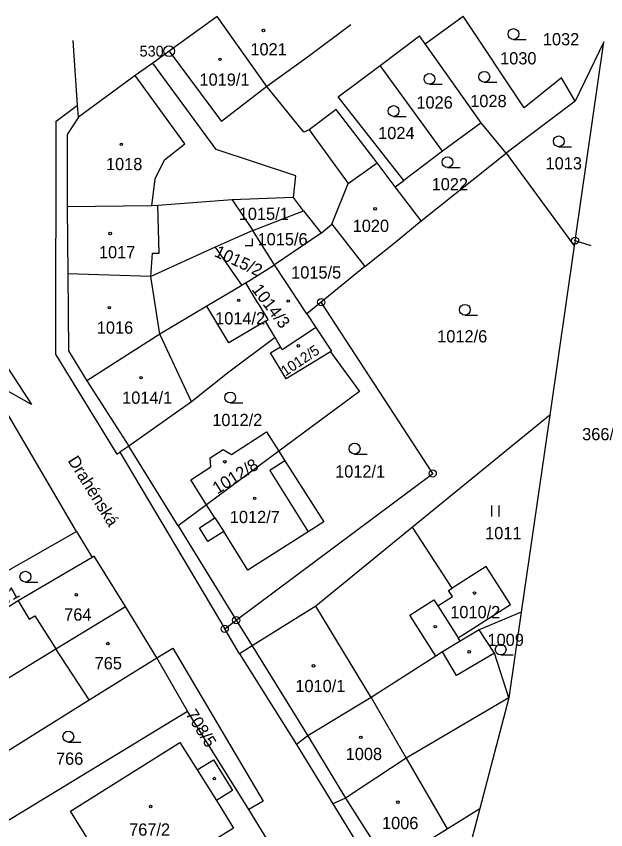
# Model space of a CAD drawing. Extents: x -776701 to -776081, y -974398 to -973771.
# Drawn here: x -776229.3 to -776147.4, y -973884.4 to -973771.3 of the extents above; entities that cross this region are included whole.
import ezdxf

# ---------------------------------------------------------------- set-up
doc = ezdxf.new("R2010")
doc.units = 0
for name, color, linetype in [('Hranice parcel', 7, 'Continuous'), ('Parcelní čísla', 7, 'Continuous'), ('Pop  PČ popisy', 7, 'Continuous'), ('Vnitřní kresba', 7, 'Continuous'), ('Značky bodu BP', 7, 'Continuous'), ('Značky budov', 7, 'Continuous'), ('Značky kultur', 7, 'Continuous')]:
    doc.layers.add(name, color=color, linetype=linetype)

msp = doc.modelspace()

# ---------------------------------------------------------------- linework, layer by layer
at = {"layer": 'Hranice parcel'}
for p, q in [((-776172.49, -973775.13), (-776167.2, -973771.3)), ((-776178.76, -973778.12), (-776173.27, -973774.04)), ((-776172.49, -973775.13), (-776173.27, -973774.04)), ((-776164.68, -973786.09), (-776172.49, -973775.13)), ((-776147.65, -973774.86), (-776151.65, -973783.1)), ((-776151.65, -973802.49), (-776147.65, -973774.86)), ((-776184.58, -973782.52), (-776178.76, -973778.12)), ((-776170.09, -973790.04), (-776178.76, -973778.12)), ((-776151.65, -973783.1), (-776153.52, -973779.87)), ((-776175.47, -973794.11), (-776184.58, -973782.52)), ((-776151.65, -973783.1), (-776161.22, -973790.34)), ((-776164.68, -973786.09), (-776170.09, -973790.04)), ((-776161.22, -973790.34), (-776164.68, -973786.09)), ((-776170.09, -973790.04), (-776175.47, -973794.11)), ((-776173.06, -973799.74), (-776161.22, -973790.34)), ((-776161.22, -973790.34), (-776151.75, -973803.2)), ((-776176.66, -973795.02), (-776179.17, -973791.67)), ((-776176.66, -973795.02), (-776175.47, -973794.11)), ((-776173.06, -973799.74), (-776176.66, -973795.02)), ((-776190.82, -973796.5), (-776199.31, -973796.81)), ((-776189.4, -973798.32), (-776190.82, -973796.5)), ((-776222.25, -973797.77), (-776222.17, -973807.08)), ((-776199.31, -973796.81), (-776196.44, -973801.08)), ((-776196.44, -973801.08), (-776189.4, -973798.32)), ((-776189.4, -973798.32), (-776186.97, -973801.45)), ((-776196.44, -973801.08), (-776201.7, -973803.4)), ((-776193.42, -973805.85), (-776196.44, -973801.08)), ((-776186.97, -973801.45), (-776185.48, -973800.19)), ((-776185.48, -973800.19), (-776180.86, -973806.09)), ((-776186.97, -973801.45), (-776193.42, -973805.85)), ((-776201.7, -973803.4), (-776198, -973808.7)), ((-776151.75, -973803.2), (-776155.16, -973826.72)), ((-776151.65, -973802.49), (-776151.75, -973803.2)), ((-776149.4, -973803.23), (-776151.65, -973802.49)), ((-776197.42, -973808.34), (-776193.42, -973805.85)), ((-776188.94, -973812.67), (-776193.42, -973805.85)), ((-776180.86, -973806.09), (-776186.94, -973811.04)), ((-776198, -973808.7), (-776202.85, -973811.59)), ((-776197.42, -973808.34), (-776198, -973808.7)), ((-776186.94, -973811.04), (-776188.94, -973812.67)), ((-776193.35, -973815.97), (-776194.71, -973813.67)), ((-776188.94, -973812.67), (-776187.7, -973814.57)), ((-776187.7, -973814.57), (-776185.53, -973817.87)), ((-776192.6, -973817.25), (-776193.35, -973815.97)), ((-776192.37, -973817.64), (-776192.6, -973817.25)), ((-776185.67, -973817.96), (-776191.83, -973821.7)), ((-776185.53, -973817.87), (-776185.67, -973817.96)), ((-776185.67, -973817.96), (-776181.61, -973823.44)), ((-776220.95, -973842.92), (-776233.34, -973821.83)), ((-776219.55, -973821.99), (-776213.69, -973831.04)), ((-776181.61, -973823.44), (-776192.82, -973831.75)), ((-776155.16, -973826.72), (-776174.27, -973842.32)), ((-776155.16, -973826.72), (-776159.12, -973854.12)), ((-776213.69, -973831.04), (-776214.95, -973831.9)), ((-776206.84, -973842.14), (-776213.69, -973831.04)), ((-776192.82, -973831.75), (-776202.88, -973839.2)), ((-776214.95, -973831.9), (-776200.36, -973856.43)), ((-776202.88, -973839.2), (-776206.84, -973842.14)), ((-776239.75, -973853.59), (-776220.95, -973842.92)), ((-776220.95, -973842.92), (-776218.81, -973846.53)), ((-776168.75, -973850.8), (-776174.27, -973842.32)), ((-776209.82, -973860.47), (-776214.18, -973853.35)), ((-776159.12, -973854.12), (-776164.99, -973856.56)), ((-776159.12, -973854.12), (-776160.84, -973866.04)), ((-776198.3, -973859.9), (-776200.36, -973856.43)), ((-776164.99, -973856.56), (-776167.63, -973858.16)), ((-776196.54, -973858.82), (-776198.3, -973859.9)), ((-776209.82, -973860.47), (-776207.58, -973859.13)), ((-776198.3, -973859.9), (-776190.39, -973872.52)), ((-776205.52, -973867.88), (-776209.82, -973860.47)), ((-776160.84, -973866.04), (-776164.9, -973881.43)), ((-776232.47, -973884.28), (-776205.52, -973867.88)), ((-776196.99, -973881.56), (-776205.52, -973867.88)), ((-776190.39, -973872.52), (-776185.35, -973880.74)), ((-776183.56, -973879.96), (-776185.35, -973880.74)), ((-776194.35, -973885.85), (-776196.99, -973881.56)), ((-776185.35, -973880.74), (-776170.9, -973904.16)), ((-776164.9, -973881.43), (-776170.9, -973904.16))]:
    msp.add_line(p, q, dxfattribs=at)
for points in [[(-776201.43, -973771.33), (-776208.1, -973776.15), (-776210.36, -973777.84)], [(-776179.17, -973791.67), (-776184.88, -973784.25), (-776188.6, -973787.1), (-776189.35, -973787.43), (-776194.52, -973781.04), (-776201.43, -973771.33)], [(-776153.52, -973779.87), (-776158.72, -973784.02), (-776167.2, -973771.3)], [(-776220.7, -973785.33), (-776220.82, -973783.65), (-776221.44, -973774.68)], [(-776210.36, -973777.84), (-776212.82, -973779.52), (-776220.7, -973785.33)], [(-776190.82, -973796.5), (-776190.45, -973793.46), (-776201.56, -973789.82), (-776210.36, -973777.84)], [(-776220.7, -973785.33), (-776222.26, -973787.71), (-776222.25, -973797.77)], [(-776185.48, -973800.19), (-776183.2, -973794.54), (-776179.17, -973791.67)], [(-776199.31, -973796.81), (-776209.67, -973797.62), (-776210.48, -973797.65), (-776222.25, -973797.77)], [(-776180.86, -973806.09), (-776176.8, -973802.85), (-776173.06, -973799.74)], [(-776201.7, -973803.4), (-776210.65, -973807.48), (-776222.17, -973807.08)], [(-776222.17, -973807.08), (-776222.09, -973817.78), (-776219.55, -973821.99)], [(-776194.71, -973813.67), (-776194.34, -973813.45), (-776195.48, -973811.56), (-776195.93, -973810.83), (-776197.42, -973808.34)], [(-776200.36, -973856.43), (-776198.76, -973855.23), (-776171.44, -973834.84), (-776186.94, -973811.04)], [(-776202.85, -973811.59), (-776209.39, -973815.48), (-776219.55, -973821.99)], [(-776194.71, -973813.67), (-776199.77, -973816.7), (-776202.85, -973811.59)], [(-776187.7, -973814.57), (-776188.03, -973814.78), (-776192.37, -973817.64)], [(-776193.35, -973815.97), (-776199.99, -973820.9), (-776205, -973824.9), (-776213.69, -973831.04)], [(-776191.83, -973821.7), (-776194, -973818.08), (-776192.6, -973817.25)], [(-776231.27, -973819.06), (-776227.23, -973825.26), (-776233.34, -973821.83)], [(-776202.88, -973839.2), (-776205.07, -973835.71), (-776202.31, -973833.94), (-776202.38, -973832.68), (-776200.57, -973831.53), (-776199.44, -973832.2), (-776194.54, -973829.06), (-776192.82, -973831.75)], [(-776192.82, -973831.75), (-776191.98, -973833.08), (-776186.58, -973841.55), (-776188.78, -973842.95), (-776197.16, -973848.28), (-776200.5, -973842.93), (-776202.71, -973844.28), (-776203.86, -973842.4), (-776201.75, -973841), (-776202.88, -973839.2)], [(-776174.27, -973842.32), (-776187.69, -973853.27), (-776196.54, -973858.82)], [(-776218.81, -973846.53), (-776229.07, -973852.55), (-776233.95, -973855.6), (-776237.38, -973857.77)], [(-776214.18, -973853.35), (-776218.51, -973846.33), (-776218.81, -973846.53)], [(-776167.63, -973858.16), (-776167.92, -973857.69), (-776160.63, -973853.06), (-776163.99, -973847.77), (-776168.75, -973850.8)], [(-776170.99, -973860.22), (-776174.64, -973854.54), (-776171.27, -973852.4), (-776170.73, -973853.25), (-776168.69, -973851.95), (-776169.23, -973851.1), (-776168.75, -973850.8)], [(-776240.99, -973869.69), (-776238.41, -973868.12), (-776223.83, -973859.23), (-776214.18, -973853.35)], [(-776160.84, -973866.04), (-776162.87, -973859.82), (-776164.99, -973856.56)], [(-776167.63, -973858.16), (-776170.07, -973859.63), (-776170.99, -973860.22)], [(-776207.58, -973859.13), (-776195, -973880.4), (-776196.99, -973881.56)], [(-776236.37, -973876.99), (-776219.2, -973866.3), (-776209.82, -973860.47)], [(-776170.99, -973860.22), (-776180, -973866), (-776188.82, -973871.31), (-776190.39, -973872.52)], [(-776160.84, -973866.04), (-776175.11, -973874.42), (-776183.56, -973879.96)], [(-776221.8, -973881.78), (-776206.58, -973872.23), (-776204.18, -973876.06), (-776201.92, -973874.65), (-776199.26, -973878.91), (-776201.52, -973880.32), (-776199.13, -973884.16), (-776214.43, -973893.65), (-776221.8, -973881.78)], [(-776183.56, -973879.96), (-776177.64, -973889.3), (-776169.41, -973884.22), (-776164.9, -973881.43)]]:
    msp.add_lwpolyline(points, dxfattribs=at)
at = {"layer": 'Vnitřní kresba'}
for p, q in [((-776182.84, -973772.51), (-776188.88, -973777.04)), ((-776208.1, -973776.15), (-776200.79, -973785.93)), ((-776188.88, -973777.04), (-776194.52, -973781.04)), ((-776205.91, -973789.03), (-776212.82, -973779.52)), ((-776194.52, -973781.04), (-776200.79, -973785.93)), ((-776223.8, -973785.86), (-776220.82, -973783.65)), ((-776223.85, -973818.37), (-776223.8, -973785.86)), ((-776188.6, -973787.1), (-776183.2, -973794.54)), ((-776208.72, -973791.24), (-776205.91, -973789.03)), ((-776210.01, -973793.89), (-776208.72, -973791.24)), ((-776210.48, -973797.65), (-776210.01, -973793.89)), ((-776209.49, -973804.22), (-776209.67, -973797.62)), ((-776210.65, -973807.48), (-776210.39, -973804.24)), ((-776210.39, -973804.24), (-776209.49, -973804.22)), ((-776209.39, -973815.48), (-776210.65, -973807.48)), ((-776205, -973824.9), (-776209.39, -973815.48)), ((-776223.85, -973818.37), (-776215.37, -973832.18)), ((-776215.37, -973832.18), (-776214.95, -973831.9)), ((-776201.75, -973841), (-776200.5, -973842.93)), ((-776206.84, -973842.14), (-776198.76, -973855.23)), ((-776229.07, -973852.55), (-776227.57, -973855.11)), ((-776180, -973866), (-776187.69, -973853.27)), ((-776170.73, -973853.25), (-776167.92, -973857.69)), ((-776227.57, -973855.11), (-776226.76, -973854.64)), ((-776226.76, -973854.64), (-776223.83, -973859.23)), ((-776198.76, -973855.23), (-776196.54, -973858.82)), ((-776196.54, -973858.82), (-776188.82, -973871.31)), ((-776219.2, -973866.3), (-776223.83, -973859.23)), ((-776168.11, -973862.93), (-776170.07, -973859.63)), ((-776162.87, -973859.82), (-776168.11, -973862.93)), ((-776180, -973866), (-776175.11, -973874.42)), ((-776188.82, -973871.31), (-776183.56, -973879.96)), ((-776175.11, -973874.42), (-776169.41, -973884.22)), ((-776204.18, -973876.06), (-776201.52, -973880.32))]:
    msp.add_line(p, q, dxfattribs=at)
msp.add_lwpolyline([(-776191.98, -973833.08), (-776194.09, -973834.42), (-776188.78, -973842.95)], dxfattribs=at)
at = {"layer": 'Značky bodu BP'}
for centre, radius in [((-776208.1, -973776.15), 0.75), ((-776208.1, -973776.15), 0.03), ((-776151.65, -973802.49), 0.5), ((-776151.65, -973802.49), 0.0303), ((-776186.94, -973811.04), 0.5), ((-776186.94, -973811.04), 0.0303), ((-776171.44, -973834.84), 0.5), ((-776171.44, -973834.84), 0.0303), ((-776198.76, -973855.23), 0.5), ((-776198.76, -973855.23), 0.0303), ((-776200.36, -973856.43), 0.5), ((-776200.36, -973856.43), 0.0303)]:
    msp.add_circle(centre, radius, dxfattribs=at)
at = {"layer": 'Značky budov'}
for centre in [(-776194.98, -973773.27), (-776201.02, -973777.28), (-776214.73, -973789.1), (-776179.44, -973798.06), (-776216.29, -973801.49), (-776198.42, -973810.79), (-776191.53, -973810.87), (-776216.4, -973811.81), (-776190.13, -973817.1), (-776212, -973821.53), (-776200.34, -973833.22), (-776196.2, -973838.3), (-776220.99, -973851.72), (-776165.62, -973851.47), (-776171.09, -973856.14), (-776216.61, -973858.49), (-776166.36, -973859.64), (-776188.02, -973861.58), (-776181.44, -973871.52), (-776201.8, -973877.25), (-776176.28, -973880.53), (-776210.66, -973881.13)]:
    msp.add_circle(centre, 0.175, dxfattribs=at)
at = {"layer": 'Značky kultur'}
for p, q in [((-776160.21, -973774.52), (-776158.46, -973774.52)), ((-776171.89, -973780.75), (-776170.14, -973780.75)), ((-776164.27, -973780.46), (-776162.52, -973780.46)), ((-776176.88, -973785.22), (-776175.13, -973785.22)), ((-776153.91, -973789.43), (-776152.16, -973789.43)), ((-776169.39, -973792.33), (-776167.64, -973792.33)), ((-776196.52, -973803.18), (-776196.52, -973802.18)), ((-776197.52, -973803.18), (-776196.52, -973803.18)), ((-776166.97, -973812.84), (-776165.22, -973812.84)), ((-776199.6, -973825.03), (-776197.85, -973825.03)), ((-776182.3, -973832.14), (-776180.55, -973832.14)), ((-776163.22, -973840.82), (-776163.22, -973839.32)), ((-776162.22, -973840.82), (-776162.22, -973839.32)), ((-776228.08, -973849.94), (-776226.33, -973849.94)), ((-776161.99, -973860.07), (-776160.24, -973860.07)), ((-776222.11, -973872.17), (-776220.36, -973872.17))]:
    msp.add_line(p, q, dxfattribs=at)
for centre in [(-776160.21, -973773.77), (-776171.89, -973780), (-776164.27, -973779.71), (-776176.88, -973784.47), (-776153.91, -973788.68), (-776169.39, -973791.58), (-776166.97, -973812.09), (-776199.6, -973824.28), (-776182.3, -973831.39), (-776228.08, -973849.19), (-776161.99, -973859.32), (-776222.11, -973871.42)]:
    msp.add_circle(centre, 0.75, dxfattribs=at)

# ---------------------------------------------------------------- texts
at = {"layer": 'Parcelní čísla'}
for s, p in [('1032', (-776156.12, -973775.34)), ('1021', (-776196.79, -973776.74)), ('1030', (-776162.07, -973777.99)), ('1019/1', (-776203.87, -973780.95)), ('1026', (-776173.71, -973784.12)), ('1028', (-776166.22, -973783.93)), ('1024', (-776179.02, -973788.38)), ('1018', (-776216.87, -973792.69)), ('1013', (-776155.75, -973792.59)), ('1022', (-776171.59, -973795.49)), ('1015/1', (-776198.41, -973799.61)), ('1020', (-776182.57, -973801.27)), ('1015/6', (-776195.79, -973803.14)), ('1017', (-776217.85, -973804.94)), ('1015/5', (-776191.12, -973807.75)), ('1014/2', (-776201.69, -973814.13)), ('1016', (-776218.15, -973815.42)), ('1012/6', (-776170.81, -973816.63)), ('1014/1', (-776214.62, -973825.16)), ('1012/2', (-776202.09, -973828.26)), ('366/1', (-776150.66, -973830.23)), ('1012/1', (-776185.01, -973835.41)), ('1012/7', (-776199.65, -973841.74)), ('1011', (-776164.15, -973843.98)), ('1010/2', (-776169, -973854.96)), ('764', (-776222.68, -973855.3)), ('1009', (-776163.82, -973858.82)), ('765', (-776218.45, -973862.07)), ('1010/1', (-776190.54, -973865.23)), ('766', (-776223.82, -973875.33)), ('1008', (-776183.54, -973874.68)), ('1006', (-776178.49, -973884.28)), ('767/2', (-776213.65, -973885.19))]:
    msp.add_text(s, height=1.7, dxfattribs=at).set_placement(p)
for s, height, rotation, p in [('1015/2', 1.7, 335, (-776201.94, -973804.6)), ('1014/3', 1.7, 307, (-776196.69, -973809.29)), ('1012/5', 1.445, 34, (-776191.93, -973821.39)), ('1012/8', 1.7, 32, (-776201.39, -973837.79)), ('763/1', 1.7, 29, (-776233.72, -973854.65)), ('708/5', 1.7, 302, (-776205.86, -973868.28))]:
    msp.add_text(s, height=height, rotation=rotation, dxfattribs=at).set_placement(p)
at = {"layer": 'Pop  PČ popisy'}
msp.add_text('Drahénská', height=1.7, rotation=302, dxfattribs=at).set_placement((-776222.25, -973833.06))
at = {"layer": 'Značky bodu BP'}
msp.add_text('530', height=1.5, dxfattribs=at).set_placement((-776212.2, -973776.9))

doc.saveas('drawing.dxf')
